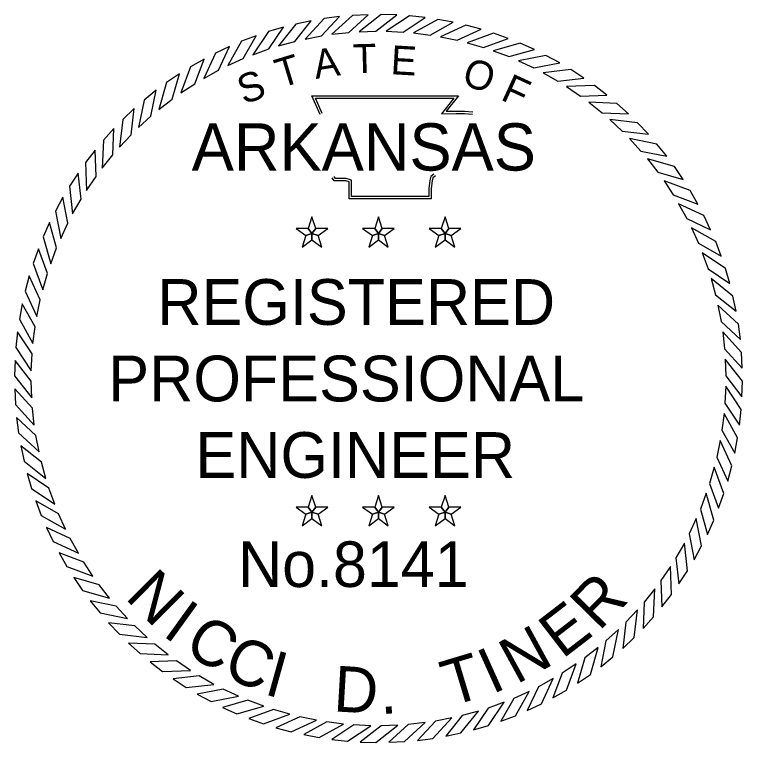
# Model space of a CAD drawing. Extents: x 1448008.9 to 1448047, y 2057056.5 to 2057079.8.
# Drawn here: x 1448044.573 to 1448047.005, y 2057075.959 to 2057078.391 of the extents above; entities that cross this region are included whole.
import ezdxf

# ---------------------------------------------------------------- set-up
doc = ezdxf.new("R2010")
doc.units = 0
doc.layers.add('G-ANNO-SYMB', color=7, linetype='Continuous')

msp = doc.modelspace()

# ---------------------------------------------------------------- linework, layer by layer
at = {"layer": 'G-ANNO-SYMB'}
for points in [[(1448045.7546, 2057078.3905), (1448045.7023, 2057078.3879), (1448045.6336, 2057078.3249), (1448045.6898, 2057078.3311)], [(1448045.85, 2057078.3895), (1448045.7978, 2057078.3909), (1448045.7243, 2057078.3336), (1448045.7808, 2057078.3354)], [(1448045.5649, 2057078.3701), (1448045.5137, 2057078.3593), (1448045.4557, 2057078.2864), (1448045.5102, 2057078.3013)], [(1448045.6593, 2057078.384), (1448045.6075, 2057078.3773), (1448045.5439, 2057078.3091), (1448045.5994, 2057078.3197)], [(1448045.9451, 2057078.3809), (1448045.8931, 2057078.3865), (1448045.8154, 2057078.3351), (1448045.8718, 2057078.3325)], [(1448046.0392, 2057078.365), (1448045.9878, 2057078.3747), (1448045.9063, 2057078.3295), (1448045.9624, 2057078.3224)], [(1448045.4718, 2057078.3488), (1448045.4216, 2057078.334), (1448045.3695, 2057078.2568), (1448045.4227, 2057078.2759)], [(1448046.1318, 2057078.3417), (1448046.0813, 2057078.3554), (1448045.9965, 2057078.3167), (1448046.0519, 2057078.3053)], [(1448045.3807, 2057078.3203), (1448045.3318, 2057078.3016), (1448045.286, 2057078.2205), (1448045.3374, 2057078.2438)], [(1448046.2223, 2057078.3113), (1448046.173, 2057078.3288), (1448046.0855, 2057078.297), (1448046.1397, 2057078.2812)], [(1448046.3101, 2057078.2738), (1448046.2624, 2057078.2952), (1448046.1726, 2057078.2703), (1448046.2254, 2057078.2503)], [(1448045.2921, 2057078.2847), (1448045.2449, 2057078.2623), (1448045.2055, 2057078.1778), (1448045.255, 2057078.205)], [(1448046.3947, 2057078.2295), (1448046.3488, 2057078.2546), (1448046.2573, 2057078.2368), (1448046.3084, 2057078.2128)], [(1448045.2066, 2057078.2422), (1448045.1613, 2057078.2162), (1448045.1286, 2057078.1289), (1448045.1758, 2057078.1599)], [(1448046.4756, 2057078.1788), (1448046.4318, 2057078.2074), (1448046.3392, 2057078.1968), (1448046.3883, 2057078.1688)], [(1448045.1247, 2057078.1932), (1448045.0815, 2057078.1637), (1448045.0558, 2057078.0741), (1448045.1004, 2057078.1088)], [(1448046.5522, 2057078.1219), (1448046.5108, 2057078.1538), (1448046.4176, 2057078.1505), (1448046.4644, 2057078.1188)], [(1448045.0468, 2057078.1379), (1448045.0061, 2057078.1051), (1448044.9875, 2057078.0138), (1448045.0293, 2057078.0518)], [(1448046.6241, 2057078.0591), (1448046.5853, 2057078.0942), (1448046.4922, 2057078.0982), (1448046.5363, 2057078.0629)], [(1448044.9736, 2057078.0767), (1448044.9356, 2057078.0408), (1448044.9242, 2057077.9483), (1448044.9629, 2057077.9895)], [(1448046.6909, 2057077.9909), (1448046.655, 2057078.0289), (1448046.5625, 2057078.0402), (1448046.6037, 2057078.0016)], [(1448044.9054, 2057078.0099), (1448044.8703, 2057077.9712), (1448044.8662, 2057077.8781), (1448044.9015, 2057077.9222)], [(1448046.7521, 2057077.9176), (1448046.7193, 2057077.9583), (1448046.628, 2057077.9769), (1448046.666, 2057077.9351)], [(1448044.8426, 2057077.938), (1448044.8107, 2057077.8966), (1448044.8139, 2057077.8035), (1448044.8457, 2057077.8502)], [(1448046.8074, 2057077.8398), (1448046.7779, 2057077.8829), (1448046.6883, 2057077.9086), (1448046.7229, 2057077.864)], [(1448044.7856, 2057077.8614), (1448044.7571, 2057077.8176), (1448044.7676, 2057077.725), (1448044.7956, 2057077.7741)], [(1448046.8564, 2057077.7578), (1448046.8304, 2057077.8032), (1448046.7431, 2057077.8358), (1448046.7741, 2057077.7886)], [(1448044.7349, 2057077.7805), (1448044.7098, 2057077.7346), (1448044.7276, 2057077.6431), (1448044.7517, 2057077.6943)], [(1448046.8988, 2057077.6723), (1448046.8764, 2057077.7196), (1448046.792, 2057077.759), (1448046.8192, 2057077.7095)], [(1448045.567, 2057077.6593), (1448045.5795, 2057077.6765), (1448045.567, 2057077.7149), (1448045.5545, 2057077.6765)], [(1448045.7893, 2057077.6593), (1448045.8018, 2057077.6765), (1448045.7893, 2057077.7149), (1448045.7768, 2057077.6765)], [(1448046.0116, 2057077.6593), (1448046.0241, 2057077.6765), (1448046.0116, 2057077.7149), (1448045.9992, 2057077.6765)], [(1448044.6907, 2057077.6959), (1448044.6693, 2057077.6482), (1448044.6942, 2057077.5584), (1448044.7141, 2057077.6113)], [(1448045.567, 2057077.6593), (1448045.5545, 2057077.6765), (1448045.5141, 2057077.6765), (1448045.5468, 2057077.6527)], [(1448045.567, 2057077.6593), (1448045.5872, 2057077.6527), (1448045.6198, 2057077.6765), (1448045.5795, 2057077.6765)], [(1448045.7893, 2057077.6593), (1448045.7768, 2057077.6765), (1448045.7364, 2057077.6765), (1448045.7691, 2057077.6527)], [(1448045.7893, 2057077.6593), (1448045.8095, 2057077.6527), (1448045.8422, 2057077.6765), (1448045.8018, 2057077.6765)], [(1448046.0116, 2057077.6593), (1448045.9992, 2057077.6765), (1448045.9588, 2057077.6765), (1448045.9914, 2057077.6527)], [(1448046.0116, 2057077.6593), (1448046.0318, 2057077.6527), (1448046.0645, 2057077.6765), (1448046.0241, 2057077.6765)], [(1448046.9344, 2057077.5837), (1448046.9158, 2057077.6326), (1448046.8347, 2057077.6785), (1448046.858, 2057077.627)], [(1448045.567, 2057077.6593), (1448045.5468, 2057077.6527), (1448045.5343, 2057077.6143), (1448045.567, 2057077.6381)], [(1448045.567, 2057077.6593), (1448045.567, 2057077.6381), (1448045.5997, 2057077.6143), (1448045.5872, 2057077.6527)], [(1448045.7893, 2057077.6593), (1448045.7691, 2057077.6527), (1448045.7566, 2057077.6143), (1448045.7893, 2057077.6381)], [(1448045.7893, 2057077.6593), (1448045.7893, 2057077.6381), (1448045.822, 2057077.6143), (1448045.8095, 2057077.6527)], [(1448046.0116, 2057077.6593), (1448045.9914, 2057077.6527), (1448045.979, 2057077.6143), (1448046.0116, 2057077.6381)], [(1448046.0116, 2057077.6593), (1448046.0116, 2057077.6381), (1448046.0443, 2057077.6143), (1448046.0318, 2057077.6527)], [(1448044.6532, 2057077.6081), (1448044.6356, 2057077.5589), (1448044.6675, 2057077.4713), (1448044.6832, 2057077.5256)], [(1448046.963, 2057077.4926), (1448046.9482, 2057077.5428), (1448046.871, 2057077.5949), (1448046.8901, 2057077.5418)], [(1448044.6227, 2057077.5176), (1448044.6091, 2057077.4672), (1448044.6477, 2057077.3824), (1448044.6591, 2057077.4377)], [(1448046.9843, 2057077.3996), (1448046.9735, 2057077.4507), (1448046.9006, 2057077.5088), (1448046.9155, 2057077.4543)], [(1448044.5994, 2057077.4251), (1448044.5898, 2057077.3737), (1448044.635, 2057077.2922), (1448044.642, 2057077.3482)], [(1448046.9982, 2057077.3051), (1448046.9915, 2057077.357), (1448046.9233, 2057077.4205), (1448046.9339, 2057077.3651)], [(1448044.5835, 2057077.3309), (1448044.5779, 2057077.2789), (1448044.6293, 2057077.2012), (1448044.632, 2057077.2577)], [(1448047.0046, 2057077.2099), (1448047.002, 2057077.2621), (1448046.9391, 2057077.3308), (1448046.9453, 2057077.2747)], [(1448044.575, 2057077.2358), (1448044.5735, 2057077.1836), (1448044.6309, 2057077.1101), (1448044.6291, 2057077.1666)], [(1448047.0036, 2057077.1144), (1448047.0051, 2057077.1667), (1448046.9477, 2057077.2401), (1448046.9495, 2057077.1837)], [(1448046.9951, 2057077.0193), (1448047.0007, 2057077.0713), (1448046.9493, 2057077.149), (1448046.9466, 2057077.0926)], [(1448044.574, 2057077.1404), (1448044.5766, 2057077.0882), (1448044.6395, 2057077.0195), (1448044.6333, 2057077.0756)], [(1448046.9792, 2057076.9252), (1448046.9888, 2057076.9766), (1448046.9436, 2057077.0581), (1448046.9366, 2057077.0021)], [(1448044.5804, 2057077.0451), (1448044.5871, 2057076.9933), (1448044.6553, 2057076.9297), (1448044.6447, 2057076.9852)], [(1448046.9559, 2057076.8326), (1448046.9696, 2057076.8831), (1448046.9309, 2057076.9679), (1448046.9195, 2057076.9126)], [(1448044.5944, 2057076.9507), (1448044.6051, 2057076.8995), (1448044.678, 2057076.8415), (1448044.6631, 2057076.896)], [(1448044.6157, 2057076.8576), (1448044.6304, 2057076.8075), (1448044.7076, 2057076.7554), (1448044.6885, 2057076.8085)], [(1448046.9254, 2057076.7421), (1448046.943, 2057076.7914), (1448046.9111, 2057076.879), (1448046.8954, 2057076.8247)], [(1448046.888, 2057076.6543), (1448046.9093, 2057076.7021), (1448046.8844, 2057076.7919), (1448046.8645, 2057076.739)], [(1448044.6442, 2057076.7665), (1448044.6628, 2057076.7177), (1448044.7439, 2057076.6718), (1448044.7207, 2057076.7233)], [(1448045.567, 2057076.7283), (1448045.5795, 2057076.7455), (1448045.567, 2057076.7839), (1448045.5545, 2057076.7455)], [(1448045.7893, 2057076.7283), (1448045.8018, 2057076.7455), (1448045.7893, 2057076.7839), (1448045.7768, 2057076.7455)], [(1448046.0116, 2057076.7283), (1448046.0241, 2057076.7455), (1448046.0116, 2057076.7839), (1448045.9992, 2057076.7455)], [(1448045.567, 2057076.7283), (1448045.5545, 2057076.7455), (1448045.5141, 2057076.7455), (1448045.5468, 2057076.7217)], [(1448045.567, 2057076.7283), (1448045.5872, 2057076.7217), (1448045.6198, 2057076.7455), (1448045.5795, 2057076.7455)], [(1448045.7893, 2057076.7283), (1448045.7768, 2057076.7455), (1448045.7364, 2057076.7455), (1448045.7691, 2057076.7217)], [(1448045.7893, 2057076.7283), (1448045.8095, 2057076.7217), (1448045.8422, 2057076.7455), (1448045.8018, 2057076.7455)], [(1448046.0116, 2057076.7283), (1448045.9992, 2057076.7455), (1448045.9588, 2057076.7455), (1448045.9914, 2057076.7217)], [(1448046.0116, 2057076.7283), (1448046.0318, 2057076.7217), (1448046.0645, 2057076.7455), (1448046.0241, 2057076.7455)], [(1448045.567, 2057076.7283), (1448045.5468, 2057076.7217), (1448045.5343, 2057076.6833), (1448045.567, 2057076.7071)], [(1448045.567, 2057076.7283), (1448045.567, 2057076.7071), (1448045.5997, 2057076.6833), (1448045.5872, 2057076.7217)], [(1448045.7893, 2057076.7283), (1448045.7691, 2057076.7217), (1448045.7566, 2057076.6833), (1448045.7893, 2057076.7071)], [(1448045.7893, 2057076.7283), (1448045.7893, 2057076.7071), (1448045.822, 2057076.6833), (1448045.8095, 2057076.7217)], [(1448046.0116, 2057076.7283), (1448045.9914, 2057076.7217), (1448045.979, 2057076.6833), (1448046.0116, 2057076.7071)], [(1448046.0116, 2057076.7283), (1448046.0116, 2057076.7071), (1448046.0443, 2057076.6833), (1448046.0318, 2057076.7217)], [(1448046.8437, 2057076.5697), (1448046.8688, 2057076.6156), (1448046.851, 2057076.7071), (1448046.8269, 2057076.656)], [(1448044.6798, 2057076.6779), (1448044.7022, 2057076.6307), (1448044.7866, 2057076.5913), (1448044.7594, 2057076.6408)], [(1448046.793, 2057076.4889), (1448046.8215, 2057076.5327), (1448046.811, 2057076.6253), (1448046.783, 2057076.5762)], [(1448044.7222, 2057076.5924), (1448044.7482, 2057076.5471), (1448044.8355, 2057076.5144), (1448044.8045, 2057076.5616)], [(1448046.736, 2057076.4123), (1448046.768, 2057076.4537), (1448046.7647, 2057076.5468), (1448046.733, 2057076.5001)], [(1448044.7712, 2057076.5105), (1448044.8007, 2057076.4673), (1448044.8903, 2057076.4416), (1448044.8557, 2057076.4863)], [(1448046.6733, 2057076.3403), (1448046.7083, 2057076.3791), (1448046.7124, 2057076.4722), (1448046.6771, 2057076.4281)], [(1448044.8265, 2057076.4327), (1448044.8593, 2057076.392), (1448044.9506, 2057076.3734), (1448044.9126, 2057076.4151)], [(1448046.605, 2057076.2735), (1448046.643, 2057076.3095), (1448046.6544, 2057076.4019), (1448046.6157, 2057076.3608)], [(1448044.8877, 2057076.3594), (1448044.9236, 2057076.3214), (1448045.0161, 2057076.31), (1448044.9749, 2057076.3487)], [(1448046.5318, 2057076.2123), (1448046.5725, 2057076.2451), (1448046.5911, 2057076.3365), (1448046.5493, 2057076.2984)], [(1448044.9545, 2057076.2912), (1448044.9933, 2057076.2561), (1448045.0864, 2057076.252), (1448045.0423, 2057076.2874)], [(1448046.454, 2057076.157), (1448046.4971, 2057076.1866), (1448046.5228, 2057076.2761), (1448046.4782, 2057076.2415)], [(1448045.0264, 2057076.2284), (1448045.0678, 2057076.1965), (1448045.161, 2057076.1997), (1448045.1142, 2057076.2315)], [(1448046.372, 2057076.108), (1448046.4174, 2057076.1341), (1448046.45, 2057076.2214), (1448046.4028, 2057076.1903)], [(1448045.1031, 2057076.1715), (1448045.1468, 2057076.1429), (1448045.2394, 2057076.1534), (1448045.1904, 2057076.1814)], [(1448046.2865, 2057076.0656), (1448046.3337, 2057076.088), (1448046.3731, 2057076.1725), (1448046.3236, 2057076.1452)], [(1448045.1839, 2057076.1207), (1448045.2298, 2057076.0957), (1448045.3213, 2057076.1135), (1448045.2702, 2057076.1375)], [(1448046.1979, 2057076.03), (1448046.2468, 2057076.0486), (1448046.2927, 2057076.1297), (1448046.2412, 2057076.1065)], [(1448045.2685, 2057076.0765), (1448045.3162, 2057076.0551), (1448045.406, 2057076.08), (1448045.3532, 2057076.1)], [(1448046.1068, 2057076.0015), (1448046.157, 2057076.0162), (1448046.2091, 2057076.0935), (1448046.1559, 2057076.0743)], [(1448045.3563, 2057076.039), (1448045.4056, 2057076.0214), (1448045.4931, 2057076.0533), (1448045.4389, 2057076.0691)], [(1448046.0137, 2057075.9802), (1448046.0649, 2057075.9909), (1448046.1229, 2057076.0639), (1448046.0684, 2057076.049)], [(1448045.4468, 2057076.0085), (1448045.4973, 2057075.9949), (1448045.5821, 2057076.0335), (1448045.5267, 2057076.045)], [(1448045.9193, 2057075.9663), (1448045.9712, 2057075.973), (1448046.0347, 2057076.0411), (1448045.9792, 2057076.0305)], [(1448045.5394, 2057075.9853), (1448045.5908, 2057075.9756), (1448045.6723, 2057076.0208), (1448045.6162, 2057076.0279)], [(1448045.6335, 2057075.9693), (1448045.6855, 2057075.9637), (1448045.7632, 2057076.0152), (1448045.7068, 2057076.0178)], [(1448045.7286, 2057075.9608), (1448045.7809, 2057075.9593), (1448045.8543, 2057076.0167), (1448045.7978, 2057076.0149)], [(1448045.8241, 2057075.9598), (1448045.8763, 2057075.9624), (1448045.945, 2057076.0254), (1448045.8888, 2057076.0192)]]:
    msp.add_lwpolyline(points, close=True, dxfattribs=at)
for points in [[(1448045.5945, 2057078.0576), (1448045.5662, 2057078.119), (1448046.0566, 2057078.1192), (1448046.0156, 2057078.0678), (1448046.0489, 2057078.0682), (1448046.0768, 2057078.0686), (1448046.1046, 2057078.0655)], [(1448045.6016, 2057078.0608), (1448045.5783, 2057078.1112), (1448046.0405, 2057078.1115), (1448045.9993, 2057078.0598), (1448046.049, 2057078.0604), (1448046.0764, 2057078.0608), (1448046.1037, 2057078.0578)], [(1448045.9744, 2057077.8581), (1448045.9641, 2057077.8497), (1448045.9605, 2057077.8365), (1448045.9576, 2057077.8101), (1448045.9576, 2057077.7835), (1448045.6994, 2057077.7835), (1448045.6994, 2057077.8215), (1448045.6994, 2057077.8374), (1448045.6817, 2057077.8428), (1448045.6458, 2057077.8428), (1448045.6412, 2057077.8499)], [(1448045.9793, 2057077.8521), (1448045.9709, 2057077.8453), (1448045.9682, 2057077.8351), (1448045.9654, 2057077.8097), (1448045.9654, 2057077.7758), (1448045.6916, 2057077.7758), (1448045.6916, 2057077.8215), (1448045.6916, 2057077.8317), (1448045.6805, 2057077.8351), (1448045.6416, 2057077.8351), (1448045.6347, 2057077.8456)]]:
    msp.add_lwpolyline(points, dxfattribs=at)

# ---------------------------------------------------------------- texts
for s, height, rotation, p in [('T', 0.0967, 1.4789, (1448045.7045, 2057078.1949)), ('A', 0.0967, 8.6788, (1448045.5796, 2057078.1756)), ('E', 0.0967, 356.672, (1448045.8283, 2057078.1919)), ('T', 0.0967, 16.9015, (1448045.4621, 2057078.145)), ('O', 0.0967, 341.2218, (1448046.0632, 2057078.1588)), ('S', 0.0967, 19.7726, (1448045.3391, 2057078.0897)), ('F', 0.0967, 335.3628, (1448046.1936, 2057078.1078)), ('N', 0.1528, 315.2676, (1448044.9399, 2057076.4419)), ('R', 0.1528, 45.478, (1448046.5257, 2057076.3284)), ('I', 0.1528, 324.2141, (1448045.0643, 2057076.3187)), ('E', 0.1528, 37.6498, (1448046.4035, 2057076.236)), ('C', 0.1528, 328.6873, (1448045.1333, 2057076.2648)), ('N', 0.1528, 28.7033, (1448046.25, 2057076.1519)), ('C', 0.1528, 336.5155, (1448045.2634, 2057076.1839)), ('I', 0.1528, 24.2301, (1448046.1688, 2057076.1191)), ('I', 0.1528, 344.3437, (1448045.4033, 2057076.1215)), ('T', 0.1528, 16.7747, (1448046.0286, 2057076.0788)), ('D', 0.1528, 356.6451, (1448045.6366, 2057076.0634)), ('.', 0.1528, 4.846, (1448045.7968, 2057076.053))]:
    msp.add_text(s, height=height, rotation=rotation, dxfattribs=at).set_placement(p)
for s, height, p in [('ARKANSAS', 0.15788, (1448045.1653, 2057077.8697)), ('REGISTERED', 0.15285, (1448045.0505, 2057077.3543)), ('PROFESSIONAL', 0.152848, (1448044.8868, 2057077.0987)), ('ENGINEER', 0.15285, (1448045.1779, 2057076.8431)), ('No.8141', 0.15225, (1448045.3204, 2057076.4787))]:
    msp.add_text(s, height=height, dxfattribs=at).set_placement(p)

doc.saveas('drawing.dxf')
